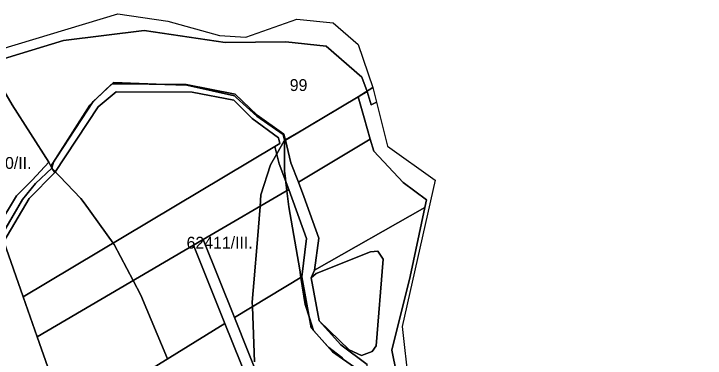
# Model space of a CAD drawing. Extents: x -522079 to -518833, y -1142400 to -1139961.
# Drawn here: x -520985.3 to -520693.7, y -1140238.4 to -1140093 of the extents above; entities that cross this region are included whole.
import ezdxf

# ---------------------------------------------------------------- set-up
doc = ezdxf.new("R2010")
doc.units = 0
for name, color, linetype in [('95560013', 7, 'Continuous'), ('95590013', 7, 'Continuous'), ('95600013', 7, 'Continuous'), ('95610013', 7, 'Continuous'), ('95630013', 7, 'Continuous'), ('95640013', 7, 'Continuous'), ('95660013', 7, 'Continuous')]:
    doc.layers.add(name, color=color, linetype=linetype)

msp = doc.modelspace()

# ---------------------------------------------------------------- linework, layer by layer
at = {"layer": '95560013'}
for points in [[(-520875.21, -1140149), (-520981.4, -1140212.45), (-520989.57, -1140189.1), (-520978.85, -1140171.05), (-520967.99, -1140160), (-520949.73, -1140132.35), (-520942.17, -1140125.91), (-520910.05, -1140126.02), (-520892.49, -1140129.42), (-520884.78, -1140137.14), (-520873.63, -1140145.32), (-520873.12, -1140147.75)], [(-520873.34, -1140156.37), (-520869.38, -1140167.25), (-520905.41, -1140188.32), (-520909.48, -1140190.7), (-520975.5, -1140229.32), (-520981.4, -1140212.45), (-520875.21, -1140149)], [(-520869.38, -1140167.25), (-520861.9, -1140187.8), (-520863.77, -1140204.01), (-520892.27, -1140221.28), (-520905.41, -1140188.32)], [(-520896.25, -1140223.69), (-520963.03, -1140264.99), (-520975.5, -1140229.32), (-520909.48, -1140190.7)], [(-520863.77, -1140204.01), (-520859.87, -1140225.61), (-520850.88, -1140235.71), (-520840.6, -1140242.88), (-520840.04, -1140256.81), (-520835.3, -1140267.04), (-520827.93, -1140275.18), (-520828.6, -1140285.19), (-520817.67, -1140300.36), (-520822.46, -1140303.46), (-520852.13, -1140321.93), (-520892.27, -1140221.28)], [(-520963.03, -1140264.99), (-520896.25, -1140223.69), (-520855.89, -1140324.19), (-520893.13, -1140348.26), (-520925.04, -1140368.05), (-520932.27, -1140351.12), (-520942.5, -1140323.7)]]:
    msp.add_lwpolyline(points, close=True, dxfattribs=at)
msp.add_lwpolyline([(-520722.28, -1140522.46), (-520749.72, -1140487.1), (-520772.84, -1140457.31), (-520777.25, -1140451.62), (-520784.75, -1140439.67), (-520830.07, -1140367.42), (-520853.68, -1140329.78), (-520855.89, -1140324.19), (-520896.25, -1140223.69), (-520909.48, -1140190.7), (-520905.41, -1140188.32), (-520892.27, -1140221.28), (-520852.13, -1140321.93), (-520849.95, -1140326.96), (-520781.06, -1140437.3), (-520773.55, -1140448.4), (-520769.04, -1140453.82), (-520745.68, -1140484.57), (-520717.71, -1140519.42), (-520693.7, -1140549.35)], dxfattribs=at)
at = {"layer": '95590013'}
for points in [[(-520870.79, -1140146.36), (-520840.13, -1140128.04), (-520837.6, -1140136.97), (-520834.99, -1140146), (-520865.3, -1140164.1), (-520868.43, -1140155.94)], [(-520811.24, -1140171.54), (-520811.93, -1140174.77), (-520858.48, -1140201.26), (-520856.72, -1140187.75), (-520863, -1140170.11), (-520865.3, -1140164.1), (-520834.99, -1140146), (-520833.53, -1140151.04), (-520821.16, -1140164.16)]]:
    msp.add_lwpolyline(points, close=True, dxfattribs=at)
at = {"layer": '95600013'}
msp.add_lwpolyline([(-520999.73, -1140195.29), (-521008.55, -1140178.79), (-521045.99, -1140153.16), (-520994.7, -1140116.62), (-520985.99, -1140131.48), (-520970.51, -1140155.67), (-520977.56, -1140163.28), (-520984.14, -1140169.84)], close=True, dxfattribs=at)
at = {"layer": '95610013'}
msp.add_lwpolyline([(-520831.58, -1140264.76), (-520835.7, -1140256.78), (-520836.21, -1140241.05), (-520847.4, -1140232.82), (-520856.59, -1140222.67), (-520843.85, -1140234.81), (-520838.62, -1140237.3), (-520834.17, -1140235.54), (-520832.49, -1140233.14), (-520829.57, -1140196.57), (-520831.74, -1140193.15), (-520834.84, -1140193.48), (-520857.8, -1140202.58), (-520859.91, -1140204.51), (-520858.48, -1140201.26), (-520811.93, -1140174.77), (-520818.11, -1140203.91), (-520825.87, -1140235.03), (-520821.91, -1140254.48), (-520810.93, -1140259.32), (-520828.22, -1140268.46)], close=True, dxfattribs=at)
at = {"layer": '95630013'}
for points in [[(-520840.13, -1140106.03), (-520833.95, -1140124.09), (-520832.38, -1140130.38), (-520834.57, -1140131.44), (-520836.28, -1140125.74), (-520838.47, -1140119.76), (-520853.61, -1140106.69), (-520870.57, -1140104.77), (-520896.13, -1140105.14), (-520930.39, -1140100.03), (-520964.33, -1140104.24), (-520996.26, -1140113.95), (-520998.41, -1140110.24), (-520941.45, -1140093.01), (-520920.41, -1140096.1), (-520898.59, -1140102.13), (-520887.39, -1140102.82), (-520865.88, -1140095.27), (-520850.56, -1140096.88)], [(-520829.57, -1140196.57), (-520832.49, -1140233.14), (-520834.17, -1140235.54), (-520838.62, -1140237.3), (-520843.85, -1140234.81), (-520856.59, -1140222.67), (-520859.91, -1140204.51), (-520857.8, -1140202.58), (-520834.84, -1140193.48), (-520831.74, -1140193.15)]]:
    msp.add_lwpolyline(points, close=True, dxfattribs=at)
for points in [[(-520840.6, -1140242.88), (-520850.88, -1140235.71), (-520859.87, -1140225.61), (-520863.77, -1140204.01), (-520861.9, -1140187.8), (-520869.38, -1140167.25), (-520873.34, -1140156.37), (-520875.21, -1140149), (-520873.12, -1140147.75), (-520873.63, -1140145.32), (-520884.78, -1140137.14), (-520892.49, -1140129.42), (-520910.05, -1140126.02), (-520942.17, -1140125.91), (-520949.73, -1140132.35), (-520967.99, -1140160), (-520969.27, -1140158.18), (-520969.72, -1140157.28), (-520951.79, -1140130), (-520943.89, -1140122.58), (-520912.67, -1140122.89), (-520891.9, -1140126.87), (-520882.74, -1140135.78), (-520871.38, -1140143.8), (-520870.79, -1140146.36), (-520868.43, -1140155.94), (-520865.3, -1140164.1), (-520863, -1140170.11), (-520856.72, -1140187.75), (-520858.48, -1140201.26), (-520859.91, -1140204.51), (-520856.59, -1140222.67), (-520847.4, -1140232.82), (-520836.21, -1140241.05)], [(-520821.91, -1140254.48), (-520825.87, -1140235.03), (-520818.11, -1140203.91), (-520811.93, -1140174.77), (-520811.24, -1140171.54), (-520821.16, -1140164.16), (-520833.53, -1140151.04), (-520834.99, -1140146), (-520837.6, -1140136.97), (-520840.13, -1140128.04), (-520836.28, -1140125.74), (-520834.57, -1140131.44), (-520832.38, -1140130.38), (-520827.76, -1140148.83), (-520807.65, -1140163.22), (-520821.47, -1140225.09), (-520818.83, -1140248.97)], [(-520999.73, -1140195.29), (-520984.14, -1140169.84), (-520977.56, -1140163.28), (-520970.51, -1140155.67), (-520969.72, -1140157.28), (-520969.27, -1140158.18), (-520976.2, -1140164.63), (-520981.64, -1140171.39), (-520997.26, -1140198.03)], [(-520997.26, -1140198.03), (-520981.64, -1140171.39), (-520976.2, -1140164.63), (-520969.27, -1140158.18), (-520967.99, -1140160), (-520978.85, -1140171.05), (-520989.57, -1140189.1)]]:
    msp.add_lwpolyline(points, dxfattribs=at)
at = {"layer": '95640013'}
msp.add_lwpolyline([(-520985.99, -1140131.48), (-520994.7, -1140116.62), (-520996.26, -1140113.95), (-520964.33, -1140104.24), (-520930.39, -1140100.03), (-520896.13, -1140105.14), (-520870.57, -1140104.77), (-520853.61, -1140106.69), (-520838.47, -1140119.76), (-520836.28, -1140125.74), (-520840.13, -1140128.04), (-520870.79, -1140146.36), (-520871.38, -1140143.8), (-520882.74, -1140135.78), (-520891.9, -1140126.87), (-520912.67, -1140122.89), (-520943.89, -1140122.58), (-520951.79, -1140130), (-520969.72, -1140157.28), (-520970.51, -1140155.67)], close=True, dxfattribs=at)
msp.add_lwpolyline([(-520989.57, -1140189.1), (-520981.4, -1140212.45), (-520975.5, -1140229.32), (-520963.03, -1140264.99), (-520942.5, -1140323.7), (-520932.27, -1140351.12), (-520925.04, -1140368.05), (-520924.44, -1140369.44), (-520915.77, -1140387.04), (-520907.24, -1140403.74), (-520902.19, -1140412.67), (-520887.82, -1140434.78), (-520876.46, -1140450.75), (-520851.49, -1140482.48), (-520837.71, -1140499.35), (-520813.81, -1140528.62)], dxfattribs=at)
at = {"layer": '95660013'}
for points in [[(-520998.41, -1140110.24), (-520941.45, -1140093.01), (-520920.41, -1140096.1), (-520898.59, -1140102.13), (-520887.39, -1140102.82), (-520865.88, -1140095.27), (-520850.56, -1140096.88), (-520840.13, -1140106.03), (-520833.95, -1140124.09), (-520840.13, -1140128.04), (-520860.65, -1140140.3), (-520870.83, -1140146.2), (-520871.09, -1140146.35), (-520871.66, -1140144), (-520882.88, -1140136.16), (-520891.57, -1140128.28), (-520892.21, -1140127.7), (-520912.38, -1140123.16), (-520921.58, -1140122.8), (-520943.31, -1140121.94), (-520946.31, -1140124.85), (-520952.08, -1140130.44), (-520953.23, -1140131.56), (-520968.64, -1140155.63), (-520969.27, -1140158.18), (-520969.72, -1140157.28), (-520970.51, -1140155.67), (-520985.99, -1140131.48)], [(-520920.51, -1140238.69), (-520931.79, -1140211.78), (-520935.01, -1140205.63), (-520943.01, -1140190.38), (-520943.45, -1140189.77), (-520955.71, -1140172.81), (-520957.05, -1140170.96), (-520969.04, -1140158.41), (-520969.27, -1140158.18), (-520968.64, -1140155.63), (-520953.23, -1140131.56), (-520952.08, -1140130.44), (-520946.31, -1140124.85), (-520943.31, -1140121.94), (-520921.58, -1140122.8), (-520912.38, -1140123.16), (-520892.21, -1140127.7), (-520891.57, -1140128.28), (-520882.88, -1140136.16), (-520871.66, -1140144), (-520871.09, -1140146.35), (-520871.25, -1140146.63), (-520874.41, -1140152.14), (-520877.03, -1140156.7), (-520881.13, -1140169.5), (-520881.48, -1140174.33), (-520882.5, -1140188.24), (-520884.08, -1140206.62), (-520884.36, -1140209.88), (-520884.77, -1140214.75), (-520884.7, -1140216.69), (-520883.86, -1140239.89)], [(-520846.54, -1140238.74), (-520846.96, -1140238.06), (-520852.43, -1140233.95), (-520852.92, -1140233.42), (-520858.95, -1140226.65), (-520860.64, -1140221.33), (-520862.45, -1140215.67), (-520864.22, -1140204.28), (-520864.73, -1140201.04), (-520869.28, -1140174.53), (-520870.11, -1140167.68), (-520870.55, -1140164.02), (-520870.87, -1140161.44), (-520871.11, -1140159.45), (-520871.09, -1140146.55), (-520871.09, -1140146.35), (-520870.83, -1140146.2), (-520860.65, -1140140.3), (-520840.13, -1140128.04), (-520833.95, -1140124.09), (-520832.38, -1140130.38), (-520827.76, -1140148.83), (-520807.65, -1140163.22), (-520821.47, -1140225.09), (-520818.83, -1140248.97)], [(-520883.86, -1140239.89), (-520884.7, -1140216.69), (-520884.77, -1140214.75), (-520884.36, -1140209.88), (-520884.08, -1140206.62), (-520882.5, -1140188.24), (-520881.48, -1140174.33), (-520881.13, -1140169.5), (-520877.03, -1140156.7), (-520874.41, -1140152.14), (-520871.25, -1140146.63), (-520871.09, -1140146.35), (-520871.09, -1140146.55), (-520871.11, -1140159.45), (-520870.87, -1140161.44), (-520870.55, -1140164.02), (-520870.11, -1140167.68), (-520869.28, -1140174.53), (-520864.73, -1140201.04), (-520864.22, -1140204.28), (-520862.45, -1140215.67), (-520860.64, -1140221.33), (-520858.95, -1140226.65), (-520852.92, -1140233.42), (-520852.43, -1140233.95), (-520846.96, -1140238.06), (-520846.54, -1140238.74)], [(-520994.97, -1140194.13), (-520981.64, -1140171.39), (-520976.2, -1140164.63), (-520969.27, -1140158.18), (-520969.04, -1140158.41), (-520957.05, -1140170.96), (-520955.71, -1140172.81), (-520943.45, -1140189.77), (-520943.01, -1140190.38), (-520935.01, -1140205.63), (-520931.79, -1140211.78), (-520920.51, -1140238.69)]]:
    msp.add_lwpolyline(points, dxfattribs=at)
msp.add_lwpolyline([(-520969.27, -1140158.18), (-520976.2, -1140164.63), (-520981.64, -1140171.39), (-520994.97, -1140194.13), (-520995.24, -1140194.59), (-520995.41, -1140194.88), (-520996, -1140195.88), (-520997.26, -1140198.03), (-520998.32, -1140199.84), (-520998.6, -1140200.31), (-520999.73, -1140195.29), (-521008.55, -1140178.79), (-521045.99, -1140153.16), (-521044.19, -1140151.88), (-520994.7, -1140116.62), (-520985.99, -1140131.48), (-520970.51, -1140155.67), (-520969.72, -1140157.28)], close=True, dxfattribs=at)

# ---------------------------------------------------------------- texts
for s, p in [('99', (-520868.93, -1140125.6)), ('35800/II.', (-521003.91, -1140158.47)), ('62411/III.', (-520912.45, -1140192.15))]:
    msp.add_text(s, height=5, rotation=360, dxfattribs=at).set_placement(p)

doc.saveas('drawing.dxf')
